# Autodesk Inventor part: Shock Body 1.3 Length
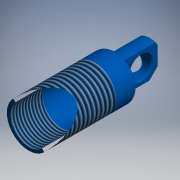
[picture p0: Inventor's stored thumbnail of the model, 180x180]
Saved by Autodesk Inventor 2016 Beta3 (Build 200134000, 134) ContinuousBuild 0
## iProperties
Shininess: 28.0
Compacted: True
Length Units: 11272
Angle Units: 11279
Time Units: 11290
Mass Units: 11286
Length Display Precision: 4
Angle Display Precision: 2
Company: Autodesk
Created: 2000-03
Part Number: Shock Body 1.3 Length
Project: Inventor Samples
User Status: IN PROGRESS
Document SubType Name: Modeling
Designer: Autodesk, Inc.
Density: 1.13 g/cm^3
Mass: 1.29919 g
Surface Area: 23.4314 cm^2
Volume: 1.14973 cm^3
Material: Nylon-6/6
Appearance: Electric Blue
Density: 0.0
Volumn: 0.0
Area: 0.0
PropertySet Name: Model Information
Control State: 0
Master: False
Checked Out: False
Title: Shock Body 1.625 Length
Author: Autodesk, Inc.
Revision Number: A
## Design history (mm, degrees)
node "Extrusion1" dims "d1" = 25.4, "d2" = 0
  sketch "Sketch2"
    geometry: C1 r 6.35 at (-3.753, -1.332)
    constraints: 1 centre point
    dimensions: "d0" = 12.7 diameter of C1
workaxis "Work Axis1"
node "Shell1" dims "d17" = 0.889
node "Fillet2" dims "d18" = 1.27
node "Extrusion2" dims "d4" = 10.16, "d5" = 0
  sketch "Sketch3"
    geometry: C1 r 6.35 at (0, 0) reference; C2 r 4.763 at (0, 0)
    constraints: 1 centre point, 1 coincident
    dimensions: "d3" = 9.525 diameter of C2
node "Extrusion3" dims "d8" = 9.525, "d9" = 0
  sketch "Sketch4"
    geometry: L1 (-1.905, 4.365)-(-1.905, -4.365); L2 (1.905, 4.365)-(1.905, -4.365); A1 r 4.763 centre (0, 0) between (-1.905, 4.365) and (-1.905, -4.365) reference
    constraints: 4 end point, 4 point on circle, 1 parallel, 1 vertical
    dimensions: "d6" = 3.81 distance between parallel lines of L2 L1; "d7" = 1.905 distance from line of A1.centre L1 (= 0.5 x d6)
node "Extrusion4" dims "d13" = 9.525, "d14" = 0
  sketch "Sketch5"
    geometry: L1 (-9.525, 1.438)-(-9.525, 7.292) reference; L2 (-17.272, 4.365)-(32.512, 4.365) reference; C1 r 3.048 at (-5.397, 4.365)
    constraints: 1 centre point, 1 point on line
    dimensions: "d11" = 4.7625 distance from line of C1.centre L1; "d12" = 6.096 diameter of C1
node "Chamfer1" dims "d15" = 0.381, "d16" = 0.381, "d26" = 45 deg
node "Fillet3" dims "d19" = 1.27
thread "Thread1" dims "d20" = 19.05, "d21" = 0
thread "Thread2" dims "d22" = 9.525, "d23" = 0
sketch "Sketch6"
  geometry: C1 r 9.593 at (10.978, -0.3)
  constraints: 1 centre point
extrude "Extrusion5" cut sketch "Sketch6" stored distance "d24" = 25.4; taper "d25" = 0 deg
workplane "Work Plane1"
body "Solid1"
